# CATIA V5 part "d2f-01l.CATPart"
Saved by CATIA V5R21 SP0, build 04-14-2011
Part number: Fin_course
Definition: SPDT-NO/NC Hinge Lever Microswitch, 100 mA @ 30 V dc
Description: SPDT-NO/NC Hinge Lever Microswitch, 100 mA @ 30 V dc
Property "REFERENCE": "D2F-01L"
Property "REFERENCE": "D2F-01L"
Property "rs_stock_number": "6160158"
Property "rs_stock_number": "6160158"
Property "SUPPLIER_NAME": "RS Components"
Property "SUPPLIER_NAME": "RS Components"
Property "Buy_Now": "https://uk.rs-online.com/web/p/products/6160158?cm_mmc=en-ds-_-mcad-_-traceparts-_-6160158'"
Property "Buy_Now": "https://uk.rs-online.com/web/p/products/6160158?cm_mmc=en-ds-_-mcad-_-traceparts-_-6160158'"
Property "SUPPLIER": "Omron"
Property "SUPPLIER": "Omron"
Property "DESIGN": "SPDT-NO/NC Hinge Lever Microswitch, 100 mA @ 30 V dc"
Property "DESIGN": "SPDT-NO/NC Hinge Lever Microswitch, 100 mA @ 30 V dc"
Property "TraceParts.PartNumber": "10-15082011-090424"
Property "TraceParts.PartTitle": "SPDT-NO/NC Hinge Lever Microswitch, 100 mA @ 30 V dc"
Property "TraceParts.InstanceId": "10-15082011-090424BT933TRIDXV33VMWLTNHFB006"
Property "TRACEPARTS": "TRACEPARTS"
Property "TraceParts.PartLanguage": "en"
Property "TraceParts.PartVersion": "1.1.3"
Bounding box of the stored display mesh (mm): x -6.4 to 6.734, y -3.5 to 11.5, z -2.9 to 2.9
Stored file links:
  C:\Users\zerma\Pictures\Stage Stomate\d2f-01l.CATPart
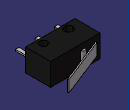
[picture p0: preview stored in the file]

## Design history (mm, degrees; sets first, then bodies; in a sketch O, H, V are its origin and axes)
AxisSystem1: origin (0, 0, 0), X (1, 0, 0), Y (0, 1, 0), Z (0, 0, 1)
Body1 "d2f-01l" (main body)
  Solid1: solid without history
